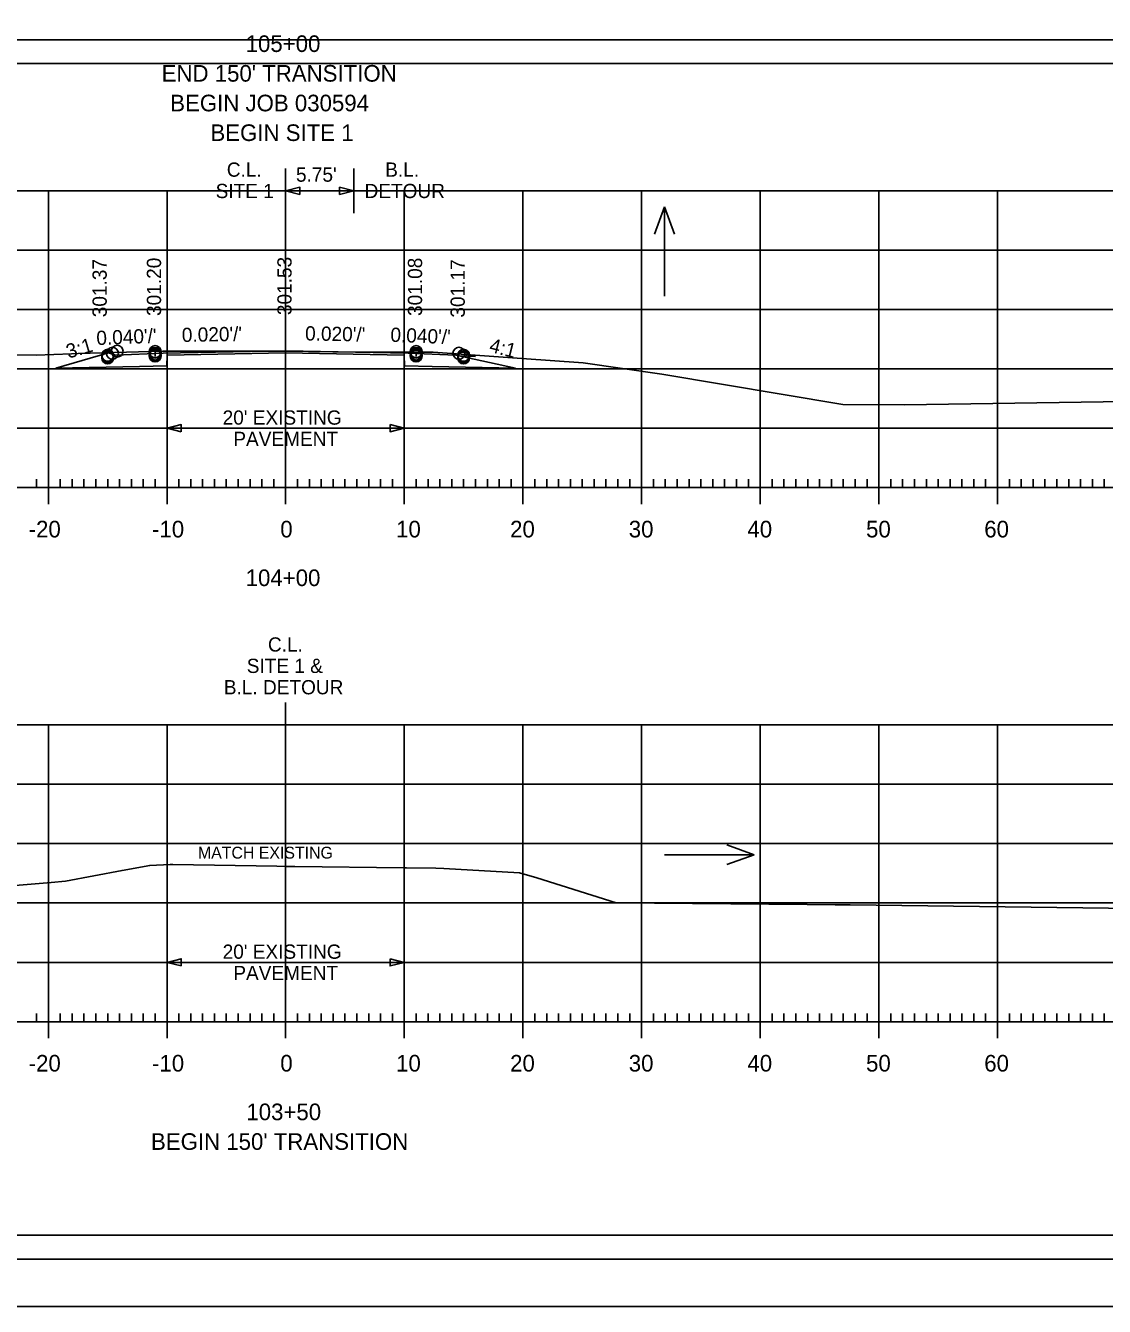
# Model space of a CAD drawing. Extents: x 1368713 to 1370673, y 380279 to 380950.
# Drawn here: x 1370130.4 to 1370221.3, y 380310.4 to 380418.3 of the extents above; entities that cross this region are included whole.
import ezdxf

# ---------------------------------------------------------------- set-up
doc = ezdxf.new("R2010")
doc.units = 0
for name, color, linetype in [('R_Alt Surface', 7, 'Continuous'), ('R_Axis', 7, 'Continuous'), ('R_Axis Annot', 7, 'Continuous'), ('R_Border', 7, 'Continuous'), ('R_Border Plan-Plan', 7, 'Continuous'), ('R_Exist Surface', 7, 'Continuous'), ('R_Fin Surface', 7, 'Continuous'), ('R_Grid', 7, 'Continuous'), ('R_No Plot', 7, 'Continuous'), ('R_ROW Annot', 7, 'Continuous'), ('R_Water Annot', 7, 'Continuous'), ('R_Xsect Elev', 7, 'Continuous'), ('R_Xsect Slope', 7, 'Continuous')]:
    doc.layers.add(name, color=color, linetype=linetype)

msp = doc.modelspace()

# ---------------------------------------------------------------- linework, layer by layer
for points in [[(1370141.28, 380391.04), (1370141.28, 380390.88), (1370141.28, 380390.73), (1370141.28, 380390.61), (1370141.28, 380390.5)], [(1370163.28, 380390.88), (1370163.28, 380390.73), (1370163.28, 380390.61), (1370163.28, 380390.5)]]:
    msp.add_lwpolyline(points)
at = {"layer": 'R_Alt Surface'}
for points in [[(1370132.92, 380389.48), (1370139.95, 380389.62), (1370142.27, 380389.67), (1370142.28, 380390.58), (1370152.28, 380390.78), (1370162.28, 380390.58), (1370162.29, 380389.67), (1370164.62, 380389.62), (1370171.64, 380389.48)], [(1370137.95, 380390.58), (1370137.95, 380390.58), (1370137.35, 380390.78)], [(1370166.62, 380390.58), (1370166.62, 380390.58), (1370171.64, 380389.48)]]:
    msp.add_lwpolyline(points, dxfattribs=at)
at = {"layer": 'R_Axis'}
for p, q in [((1370132.28, 380378.02), (1370132.28, 380380.82)), ((1370142.28, 380378.02), (1370142.28, 380380.82)), ((1370152.28, 380378.02), (1370152.28, 380380.82)), ((1370162.28, 380378.02), (1370162.28, 380380.82)), ((1370172.28, 380378.02), (1370172.28, 380380.82)), ((1370182.28, 380378.02), (1370182.28, 380380.82)), ((1370192.28, 380378.02), (1370192.28, 380380.82)), ((1370202.28, 380378.02), (1370202.28, 380380.82)), ((1370212.28, 380378.02), (1370212.28, 380380.82)), ((1370012.28, 380379.42), (1370292.28, 380379.42)), ((1370131.28, 380379.42), (1370131.28, 380380.12)), ((1370133.28, 380379.42), (1370133.28, 380380.12)), ((1370134.28, 380379.42), (1370134.28, 380380.12)), ((1370135.28, 380379.42), (1370135.28, 380380.12)), ((1370136.28, 380379.42), (1370136.28, 380380.12)), ((1370137.28, 380379.42), (1370137.28, 380380.12)), ((1370138.28, 380379.42), (1370138.28, 380380.12)), ((1370139.28, 380379.42), (1370139.28, 380380.12)), ((1370140.28, 380379.42), (1370140.28, 380380.12)), ((1370141.28, 380379.42), (1370141.28, 380380.12)), ((1370143.28, 380379.42), (1370143.28, 380380.12)), ((1370144.28, 380379.42), (1370144.28, 380380.12)), ((1370145.28, 380379.42), (1370145.28, 380380.12)), ((1370146.28, 380379.42), (1370146.28, 380380.12)), ((1370147.28, 380379.42), (1370147.28, 380380.12)), ((1370148.28, 380379.42), (1370148.28, 380380.12)), ((1370149.28, 380379.42), (1370149.28, 380380.12)), ((1370150.28, 380379.42), (1370150.28, 380380.12)), ((1370151.28, 380379.42), (1370151.28, 380380.12)), ((1370153.28, 380379.42), (1370153.28, 380380.12)), ((1370154.28, 380379.42), (1370154.28, 380380.12)), ((1370155.28, 380379.42), (1370155.28, 380380.12)), ((1370156.28, 380379.42), (1370156.28, 380380.12)), ((1370157.28, 380379.42), (1370157.28, 380380.12)), ((1370158.28, 380379.42), (1370158.28, 380380.12)), ((1370159.28, 380379.42), (1370159.28, 380380.12)), ((1370160.28, 380379.42), (1370160.28, 380380.12)), ((1370161.28, 380379.42), (1370161.28, 380380.12)), ((1370163.28, 380379.42), (1370163.28, 380380.12)), ((1370164.28, 380379.42), (1370164.28, 380380.12)), ((1370165.28, 380379.42), (1370165.28, 380380.12)), ((1370166.28, 380379.42), (1370166.28, 380380.12)), ((1370167.28, 380379.42), (1370167.28, 380380.12)), ((1370168.28, 380379.42), (1370168.28, 380380.12)), ((1370169.28, 380379.42), (1370169.28, 380380.12)), ((1370170.28, 380379.42), (1370170.28, 380380.12)), ((1370171.28, 380379.42), (1370171.28, 380380.12)), ((1370173.28, 380379.42), (1370173.28, 380380.12)), ((1370174.28, 380379.42), (1370174.28, 380380.12)), ((1370175.28, 380379.42), (1370175.28, 380380.12)), ((1370176.28, 380379.42), (1370176.28, 380380.12)), ((1370177.28, 380379.42), (1370177.28, 380380.12)), ((1370178.28, 380379.42), (1370178.28, 380380.12)), ((1370179.28, 380379.42), (1370179.28, 380380.12)), ((1370180.28, 380379.42), (1370180.28, 380380.12)), ((1370181.28, 380379.42), (1370181.28, 380380.12)), ((1370183.28, 380379.42), (1370183.28, 380380.12)), ((1370184.28, 380379.42), (1370184.28, 380380.12)), ((1370185.28, 380379.42), (1370185.28, 380380.12)), ((1370186.28, 380379.42), (1370186.28, 380380.12)), ((1370187.28, 380379.42), (1370187.28, 380380.12)), ((1370188.28, 380379.42), (1370188.28, 380380.12)), ((1370189.28, 380379.42), (1370189.28, 380380.12)), ((1370190.28, 380379.42), (1370190.28, 380380.12)), ((1370191.28, 380379.42), (1370191.28, 380380.12)), ((1370193.28, 380379.42), (1370193.28, 380380.12)), ((1370194.28, 380379.42), (1370194.28, 380380.12)), ((1370195.28, 380379.42), (1370195.28, 380380.12)), ((1370196.28, 380379.42), (1370196.28, 380380.12)), ((1370197.28, 380379.42), (1370197.28, 380380.12)), ((1370198.28, 380379.42), (1370198.28, 380380.12)), ((1370199.28, 380379.42), (1370199.28, 380380.12)), ((1370200.28, 380379.42), (1370200.28, 380380.12)), ((1370201.28, 380379.42), (1370201.28, 380380.12)), ((1370203.28, 380379.42), (1370203.28, 380380.12)), ((1370204.28, 380379.42), (1370204.28, 380380.12)), ((1370205.28, 380379.42), (1370205.28, 380380.12)), ((1370206.28, 380379.42), (1370206.28, 380380.12)), ((1370207.28, 380379.42), (1370207.28, 380380.12)), ((1370208.28, 380379.42), (1370208.28, 380380.12)), ((1370209.28, 380379.42), (1370209.28, 380380.12)), ((1370210.28, 380379.42), (1370210.28, 380380.12)), ((1370211.28, 380379.42), (1370211.28, 380380.12)), ((1370213.28, 380379.42), (1370213.28, 380380.12)), ((1370214.28, 380379.42), (1370214.28, 380380.12)), ((1370215.28, 380379.42), (1370215.28, 380380.12)), ((1370216.28, 380379.42), (1370216.28, 380380.12)), ((1370217.28, 380379.42), (1370217.28, 380380.12)), ((1370218.28, 380379.42), (1370218.28, 380380.12)), ((1370219.28, 380379.42), (1370219.28, 380380.12)), ((1370220.28, 380379.42), (1370220.28, 380380.12)), ((1370221.28, 380379.42), (1370221.28, 380380.12)), ((1370131.28, 380334.42), (1370131.28, 380335.12)), ((1370132.28, 380333.02), (1370132.28, 380335.82)), ((1370133.28, 380334.42), (1370133.28, 380335.12)), ((1370134.28, 380334.42), (1370134.28, 380335.12)), ((1370135.28, 380334.42), (1370135.28, 380335.12)), ((1370136.28, 380334.42), (1370136.28, 380335.12)), ((1370137.28, 380334.42), (1370137.28, 380335.12)), ((1370138.28, 380334.42), (1370138.28, 380335.12)), ((1370139.28, 380334.42), (1370139.28, 380335.12)), ((1370140.28, 380334.42), (1370140.28, 380335.12)), ((1370141.28, 380334.42), (1370141.28, 380335.12)), ((1370142.28, 380333.02), (1370142.28, 380335.82)), ((1370143.28, 380334.42), (1370143.28, 380335.12)), ((1370144.28, 380334.42), (1370144.28, 380335.12)), ((1370145.28, 380334.42), (1370145.28, 380335.12)), ((1370146.28, 380334.42), (1370146.28, 380335.12)), ((1370147.28, 380334.42), (1370147.28, 380335.12)), ((1370148.28, 380334.42), (1370148.28, 380335.12)), ((1370149.28, 380334.42), (1370149.28, 380335.12)), ((1370150.28, 380334.42), (1370150.28, 380335.12)), ((1370151.28, 380334.42), (1370151.28, 380335.12)), ((1370152.28, 380333.02), (1370152.28, 380335.82)), ((1370153.28, 380334.42), (1370153.28, 380335.12)), ((1370154.28, 380334.42), (1370154.28, 380335.12)), ((1370155.28, 380334.42), (1370155.28, 380335.12)), ((1370156.28, 380334.42), (1370156.28, 380335.12)), ((1370157.28, 380334.42), (1370157.28, 380335.12)), ((1370158.28, 380334.42), (1370158.28, 380335.12)), ((1370159.28, 380334.42), (1370159.28, 380335.12)), ((1370160.28, 380334.42), (1370160.28, 380335.12)), ((1370161.28, 380334.42), (1370161.28, 380335.12)), ((1370162.28, 380333.02), (1370162.28, 380335.82)), ((1370163.28, 380334.42), (1370163.28, 380335.12)), ((1370164.28, 380334.42), (1370164.28, 380335.12)), ((1370165.28, 380334.42), (1370165.28, 380335.12)), ((1370166.28, 380334.42), (1370166.28, 380335.12)), ((1370167.28, 380334.42), (1370167.28, 380335.12)), ((1370168.28, 380334.42), (1370168.28, 380335.12)), ((1370169.28, 380334.42), (1370169.28, 380335.12)), ((1370170.28, 380334.42), (1370170.28, 380335.12)), ((1370171.28, 380334.42), (1370171.28, 380335.12)), ((1370172.28, 380333.02), (1370172.28, 380335.82)), ((1370173.28, 380334.42), (1370173.28, 380335.12)), ((1370174.28, 380334.42), (1370174.28, 380335.12)), ((1370175.28, 380334.42), (1370175.28, 380335.12)), ((1370176.28, 380334.42), (1370176.28, 380335.12)), ((1370177.28, 380334.42), (1370177.28, 380335.12)), ((1370178.28, 380334.42), (1370178.28, 380335.12)), ((1370179.28, 380334.42), (1370179.28, 380335.12)), ((1370180.28, 380334.42), (1370180.28, 380335.12)), ((1370181.28, 380334.42), (1370181.28, 380335.12)), ((1370182.28, 380333.02), (1370182.28, 380335.82)), ((1370183.28, 380334.42), (1370183.28, 380335.12)), ((1370184.28, 380334.42), (1370184.28, 380335.12)), ((1370185.28, 380334.42), (1370185.28, 380335.12)), ((1370186.28, 380334.42), (1370186.28, 380335.12)), ((1370187.28, 380334.42), (1370187.28, 380335.12)), ((1370188.28, 380334.42), (1370188.28, 380335.12)), ((1370189.28, 380334.42), (1370189.28, 380335.12)), ((1370190.28, 380334.42), (1370190.28, 380335.12)), ((1370191.28, 380334.42), (1370191.28, 380335.12)), ((1370192.28, 380333.02), (1370192.28, 380335.82)), ((1370193.28, 380334.42), (1370193.28, 380335.12)), ((1370194.28, 380334.42), (1370194.28, 380335.12)), ((1370195.28, 380334.42), (1370195.28, 380335.12)), ((1370196.28, 380334.42), (1370196.28, 380335.12)), ((1370197.28, 380334.42), (1370197.28, 380335.12)), ((1370198.28, 380334.42), (1370198.28, 380335.12)), ((1370199.28, 380334.42), (1370199.28, 380335.12)), ((1370200.28, 380334.42), (1370200.28, 380335.12)), ((1370201.28, 380334.42), (1370201.28, 380335.12)), ((1370202.28, 380333.02), (1370202.28, 380335.82)), ((1370203.28, 380334.42), (1370203.28, 380335.12)), ((1370204.28, 380334.42), (1370204.28, 380335.12)), ((1370205.28, 380334.42), (1370205.28, 380335.12)), ((1370206.28, 380334.42), (1370206.28, 380335.12)), ((1370207.28, 380334.42), (1370207.28, 380335.12)), ((1370208.28, 380334.42), (1370208.28, 380335.12)), ((1370209.28, 380334.42), (1370209.28, 380335.12)), ((1370210.28, 380334.42), (1370210.28, 380335.12)), ((1370211.28, 380334.42), (1370211.28, 380335.12)), ((1370212.28, 380333.02), (1370212.28, 380335.82)), ((1370213.28, 380334.42), (1370213.28, 380335.12)), ((1370214.28, 380334.42), (1370214.28, 380335.12)), ((1370215.28, 380334.42), (1370215.28, 380335.12)), ((1370216.28, 380334.42), (1370216.28, 380335.12)), ((1370217.28, 380334.42), (1370217.28, 380335.12)), ((1370218.28, 380334.42), (1370218.28, 380335.12)), ((1370219.28, 380334.42), (1370219.28, 380335.12)), ((1370220.28, 380334.42), (1370220.28, 380335.12)), ((1370221.28, 380334.42), (1370221.28, 380335.12)), ((1370012.28, 380334.42), (1370292.28, 380334.42))]:
    msp.add_line(p, q, dxfattribs=at)
at = {"layer": 'R_Border'}
msp.add_line((1370310.46, 380314.42), (1369994.28, 380314.42), dxfattribs=at)
at = {"layer": 'R_Border Plan-Plan'}
msp.add_line((1369994.28, 380417.15), (1370310.46, 380417.15), dxfattribs=at)
at = {"layer": 'R_Exist Surface'}
for points in [[(1370128.18, 380390.61), (1370131.25, 380390.58), (1370134.22, 380390.7), (1370134.8, 380390.72), (1370141.93, 380390.9), (1370146.06, 380390.91), (1370152.14, 380390.9), (1370156.26, 380390.87), (1370162.69, 380390.84), (1370163.85, 380390.84), (1370164.72, 380390.84), (1370172.18, 380390.29), (1370177.37, 380389.92), (1370184, 380388.97), (1370199.24, 380386.42), (1370204.44, 380386.39), (1370228.63, 380386.76), (1370253.7, 380386.83), (1370266.87, 380386.8), (1370292.28, 380386.76)], [(1370128.46, 380345.81), (1370132.53, 380346.16), (1370133.73, 380346.26), (1370138.5, 380347.16), (1370140.82, 380347.58), (1370142.55, 380347.65), (1370142.76, 380347.66), (1370151.53, 380347.51), (1370152.29, 380347.5), (1370153.06, 380347.49), (1370162.25, 380347.38), (1370162.47, 380347.37), (1370164.93, 380347.35), (1370165.6, 380347.32), (1370171.98, 380346.96), (1370173.44, 380346.54), (1370180.13, 380344.43), (1370196.24, 380344.3), (1370198.59, 380344.27), (1370199.87, 380344.26), (1370228.17, 380343.91)]]:
    msp.add_lwpolyline(points, dxfattribs=at)
at = {"layer": 'R_Fin Surface'}
for points in [[(1370132.92, 380389.48), (1370137.35, 380390.78), (1370137.95, 380390.58), (1370141.95, 380390.74), (1370152.28, 380390.95), (1370162.62, 380390.74), (1370166.62, 380390.58), (1370171.64, 380389.48)], [(1370137.95, 380390.58), (1370141.95, 380390.74), (1370152.28, 380390.95), (1370162.62, 380390.74), (1370166.62, 380390.58)], [(1370166.93, 380390.52), (1370168.28, 380390.46)]]:
    msp.add_lwpolyline(points, dxfattribs=at)
at = {"layer": 'R_Grid'}
for p, q in [((1370012.28, 380404.42), (1370292.28, 380404.42)), ((1370132.28, 380379.42), (1370132.28, 380404.42)), ((1370142.28, 380379.42), (1370142.28, 380404.42)), ((1370152.28, 380379.42), (1370152.28, 380404.42)), ((1370162.28, 380379.42), (1370162.28, 380404.42)), ((1370172.28, 380379.42), (1370172.28, 380404.42)), ((1370182.28, 380379.42), (1370182.28, 380404.42)), ((1370192.28, 380379.42), (1370192.28, 380404.42)), ((1370202.28, 380379.42), (1370202.28, 380404.42)), ((1370212.28, 380379.42), (1370212.28, 380404.42)), ((1370012.28, 380399.42), (1370292.28, 380399.42)), ((1370012.28, 380394.42), (1370292.28, 380394.42)), ((1370012.28, 380389.42), (1370292.28, 380389.42)), ((1370012.28, 380384.42), (1370292.28, 380384.42)), ((1370012.28, 380379.42), (1370292.28, 380379.42)), ((1370012.28, 380359.42), (1370292.28, 380359.42)), ((1370132.28, 380334.42), (1370132.28, 380359.42)), ((1370142.28, 380334.42), (1370142.28, 380359.42)), ((1370152.28, 380334.42), (1370152.28, 380359.42)), ((1370162.28, 380334.42), (1370162.28, 380359.42)), ((1370172.28, 380334.42), (1370172.28, 380359.42)), ((1370182.28, 380334.42), (1370182.28, 380359.42)), ((1370192.28, 380334.42), (1370192.28, 380359.42)), ((1370202.28, 380334.42), (1370202.28, 380359.42)), ((1370212.28, 380334.42), (1370212.28, 380359.42)), ((1370012.28, 380354.42), (1370292.28, 380354.42)), ((1370012.28, 380349.42), (1370292.28, 380349.42)), ((1370012.28, 380344.42), (1370292.28, 380344.42)), ((1370012.28, 380339.42), (1370292.28, 380339.42)), ((1370012.28, 380334.42), (1370292.28, 380334.42))]:
    msp.add_line(p, q, dxfattribs=at)
at = {"layer": 'R_No Plot'}
for points in [[(1369981.88, 380523.77), (1370315.22, 380523.77), (1370315.22, 380310.43), (1369981.88, 380310.43)], [(1369996.28, 380517.88), (1370245.82, 380517.88), (1370245.82, 380508), (1370263.36, 380508), (1370287.46, 380508), (1370287.46, 380485.66), (1370308.46, 380485.66), (1370308.46, 380316.42), (1369996.28, 380316.42)], [(1369996.28, 380415.15), (1370308.46, 380415.15), (1370308.46, 380316.42), (1369996.28, 380316.42)]]:
    msp.add_lwpolyline(points, close=True, dxfattribs=at)
for centre in [(1370137.28, 380390.57), (1370137.28, 380390.57), (1370137.68, 380390.74), (1370138.08, 380390.91), (1370141.28, 380390.88), (1370141.28, 380390.73), (1370141.28, 380390.73), (1370141.28, 380390.61), (1370163.28, 380390.88), (1370163.28, 380390.73), (1370163.28, 380390.73), (1370163.28, 380390.61), (1370166.88, 380390.74), (1370167.28, 380390.57), (1370167.28, 380390.57), (1370137.28, 380390.45), (1370137.28, 380390.34), (1370141.28, 380390.5), (1370163.28, 380390.5), (1370167.28, 380390.45), (1370167.28, 380390.34)]:
    msp.add_circle(centre, 0.5, dxfattribs=at)
at = {"layer": 'R_ROW Annot'}
for p, q in [((1370152.28, 380402.53), (1370152.28, 380406.3)), ((1370158.03, 380402.53), (1370158.03, 380406.3)), ((1370158.03, 380404.42), (1370152.28, 380404.42)), ((1370142.28, 380382.53), (1370142.28, 380386.3)), ((1370162.28, 380382.53), (1370162.28, 380386.3)), ((1370162.28, 380384.42), (1370142.28, 380384.42)), ((1370152.28, 380357.53), (1370152.28, 380361.3)), ((1370142.28, 380337.53), (1370142.28, 380341.3)), ((1370162.28, 380337.53), (1370162.28, 380341.3)), ((1370162.28, 380339.42), (1370142.28, 380339.42))]:
    msp.add_line(p, q, dxfattribs=at)
for points in [[(1370153.48, 380404.12), (1370152.28, 380404.42), (1370153.48, 380404.72)], [(1370156.83, 380404.72), (1370158.03, 380404.42), (1370156.83, 380404.12)], [(1370143.48, 380384.12), (1370142.28, 380384.42), (1370143.48, 380384.72)], [(1370161.08, 380384.72), (1370162.28, 380384.42), (1370161.08, 380384.12)], [(1370143.48, 380339.12), (1370142.28, 380339.42), (1370143.48, 380339.72)], [(1370161.08, 380339.72), (1370162.28, 380339.42), (1370161.08, 380339.12)]]:
    msp.add_lwpolyline(points, close=True, dxfattribs=at)
at = {"layer": 'R_Water Annot'}
for p, q in [((1370184.22, 380403.08), (1370183.38, 380400.78)), ((1370184.22, 380395.54), (1370184.22, 380403.08)), ((1370184.22, 380403.08), (1370185.06, 380400.78)), ((1370191.76, 380348.49), (1370189.46, 380349.33)), ((1370184.22, 380348.49), (1370191.76, 380348.49)), ((1370191.76, 380348.49), (1370189.46, 380347.65))]:
    msp.add_line(p, q, dxfattribs=at)

# ---------------------------------------------------------------- texts
at = {"layer": 'R_Axis Annot'}
for s, p in [('105+00', (1370148.91, 380416.12)), ("END 150' TRANSITION", (1370141.83, 380413.62)), ('BEGIN JOB 030594', (1370142.55, 380411.12)), ('BEGIN SITE 1', (1370145.94, 380408.62)), ('-20', (1370130.62, 380375.22)), ('-10', (1370141.02, 380375.22)), ('0', (1370151.83, 380375.22)), ('10', (1370161.59, 380375.22)), ('20', (1370171.2, 380375.22)), ('30', (1370181.2, 380375.22)), ('40', (1370191.2, 380375.22)), ('50', (1370201.2, 380375.22)), ('60', (1370211.16, 380375.22)), ('104+00', (1370148.91, 380371.12)), ('-20', (1370130.62, 380330.22)), ('-10', (1370141.02, 380330.22)), ('0', (1370151.83, 380330.22)), ('10', (1370161.59, 380330.22)), ('20', (1370171.2, 380330.22)), ('30', (1370181.2, 380330.22)), ('40', (1370191.2, 380330.22)), ('50', (1370201.2, 380330.22)), ('60', (1370211.16, 380330.22)), ('103+50', (1370148.97, 380326.12)), ("BEGIN 150' TRANSITION", (1370140.93, 380323.62))]:
    msp.add_text(s, height=1.4, dxfattribs=at).set_placement(p)
at = {"layer": 'R_ROW Annot'}
for s, p in [('C.L.', (1370147.32, 380405.61)), ("5.75'", (1370153.15, 380405.19)), ('B.L.', (1370160.67, 380405.61)), ('SITE 1', (1370146.38, 380403.81)), ('DETOUR', (1370158.93, 380403.81)), ("20' EXISTING", (1370146.97, 380384.72)), ('PAVEMENT', (1370147.87, 380382.92)), ('C.L.', (1370150.79, 380365.6)), ('SITE 1 &', (1370149, 380363.8)), ('B.L. DETOUR', (1370147.07, 380362)), ("20' EXISTING", (1370146.97, 380339.72)), ('PAVEMENT', (1370147.87, 380337.92))]:
    msp.add_text(s, height=1.2, dxfattribs=at).set_placement(p)
at = {"layer": 'R_Xsect Elev'}
for s, p in [('301.20', (1370141.78, 380393.88)), ('301.53', (1370152.78, 380393.95)), ('301.08', (1370163.78, 380393.88)), ('301.37', (1370137.2, 380393.77)), ('301.17', (1370167.38, 380393.74))]:
    msp.add_text(s, height=1.2, rotation=90, dxfattribs=at).set_placement(p)
at = {"layer": 'R_Xsect Slope'}
for s, rotation, p in [("0.040'/'", 2.2906, (1370136.35, 380391.42)), ("0.020'/'", 1.1458, (1370143.54, 380391.68)), ("0.020'/'", 358.8542, (1370153.91, 380391.82)), ("0.040'/'", 357.7094, (1370161.09, 380391.71)), ('3:1', 16.3679, (1370133.98, 380390.28)), ('4:1', 345.8073, (1370169.37, 380390.87))]:
    msp.add_text(s, height=1.2, rotation=rotation, dxfattribs=at).set_placement(p)
msp.add_text('MATCH EXISTING', height=1, dxfattribs=at).set_placement((1370144.89, 380348.16))

doc.saveas('drawing.dxf')
